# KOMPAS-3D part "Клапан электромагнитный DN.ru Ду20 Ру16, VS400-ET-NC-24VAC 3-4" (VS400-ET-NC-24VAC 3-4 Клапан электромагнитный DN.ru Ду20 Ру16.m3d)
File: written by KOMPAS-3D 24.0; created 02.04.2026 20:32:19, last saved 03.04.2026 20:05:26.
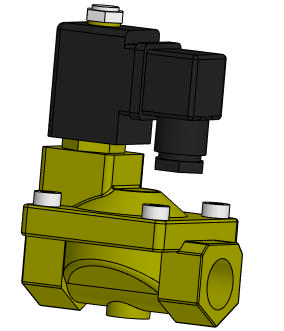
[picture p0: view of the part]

Document properties: Автор: artio; Полное имя файла: C:\Users\artio\OneDrive\Рабочий стол\Клапан электромагнитный DN.ru\VS400-ET-NC\VS400-ET-NC-24VAC 3-4 Клапан электромагнитный DN.ru Ду20 Ру16.m3d

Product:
- Body: Тело 1  | qty 1
    Масса: 1.210539
- Part/product: Клапан электромагнитный DN.ru Ду20 Ру16  | designation VS400-ET-NC-24VAC 3-4
    Масса: 0.954
    Раздел спецификации: Прочие изделия
    Примечание: D130-05488
    additional columns: ef56311e-7521-43dc-8291-0e6108b3d81d; VS400-ET-NC-220VAC 3-4; artio; c; Шероховатость не задана; Да

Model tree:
1. Операция без истории:1

Expressions: VS400-ET-NC-24VAC 3-4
